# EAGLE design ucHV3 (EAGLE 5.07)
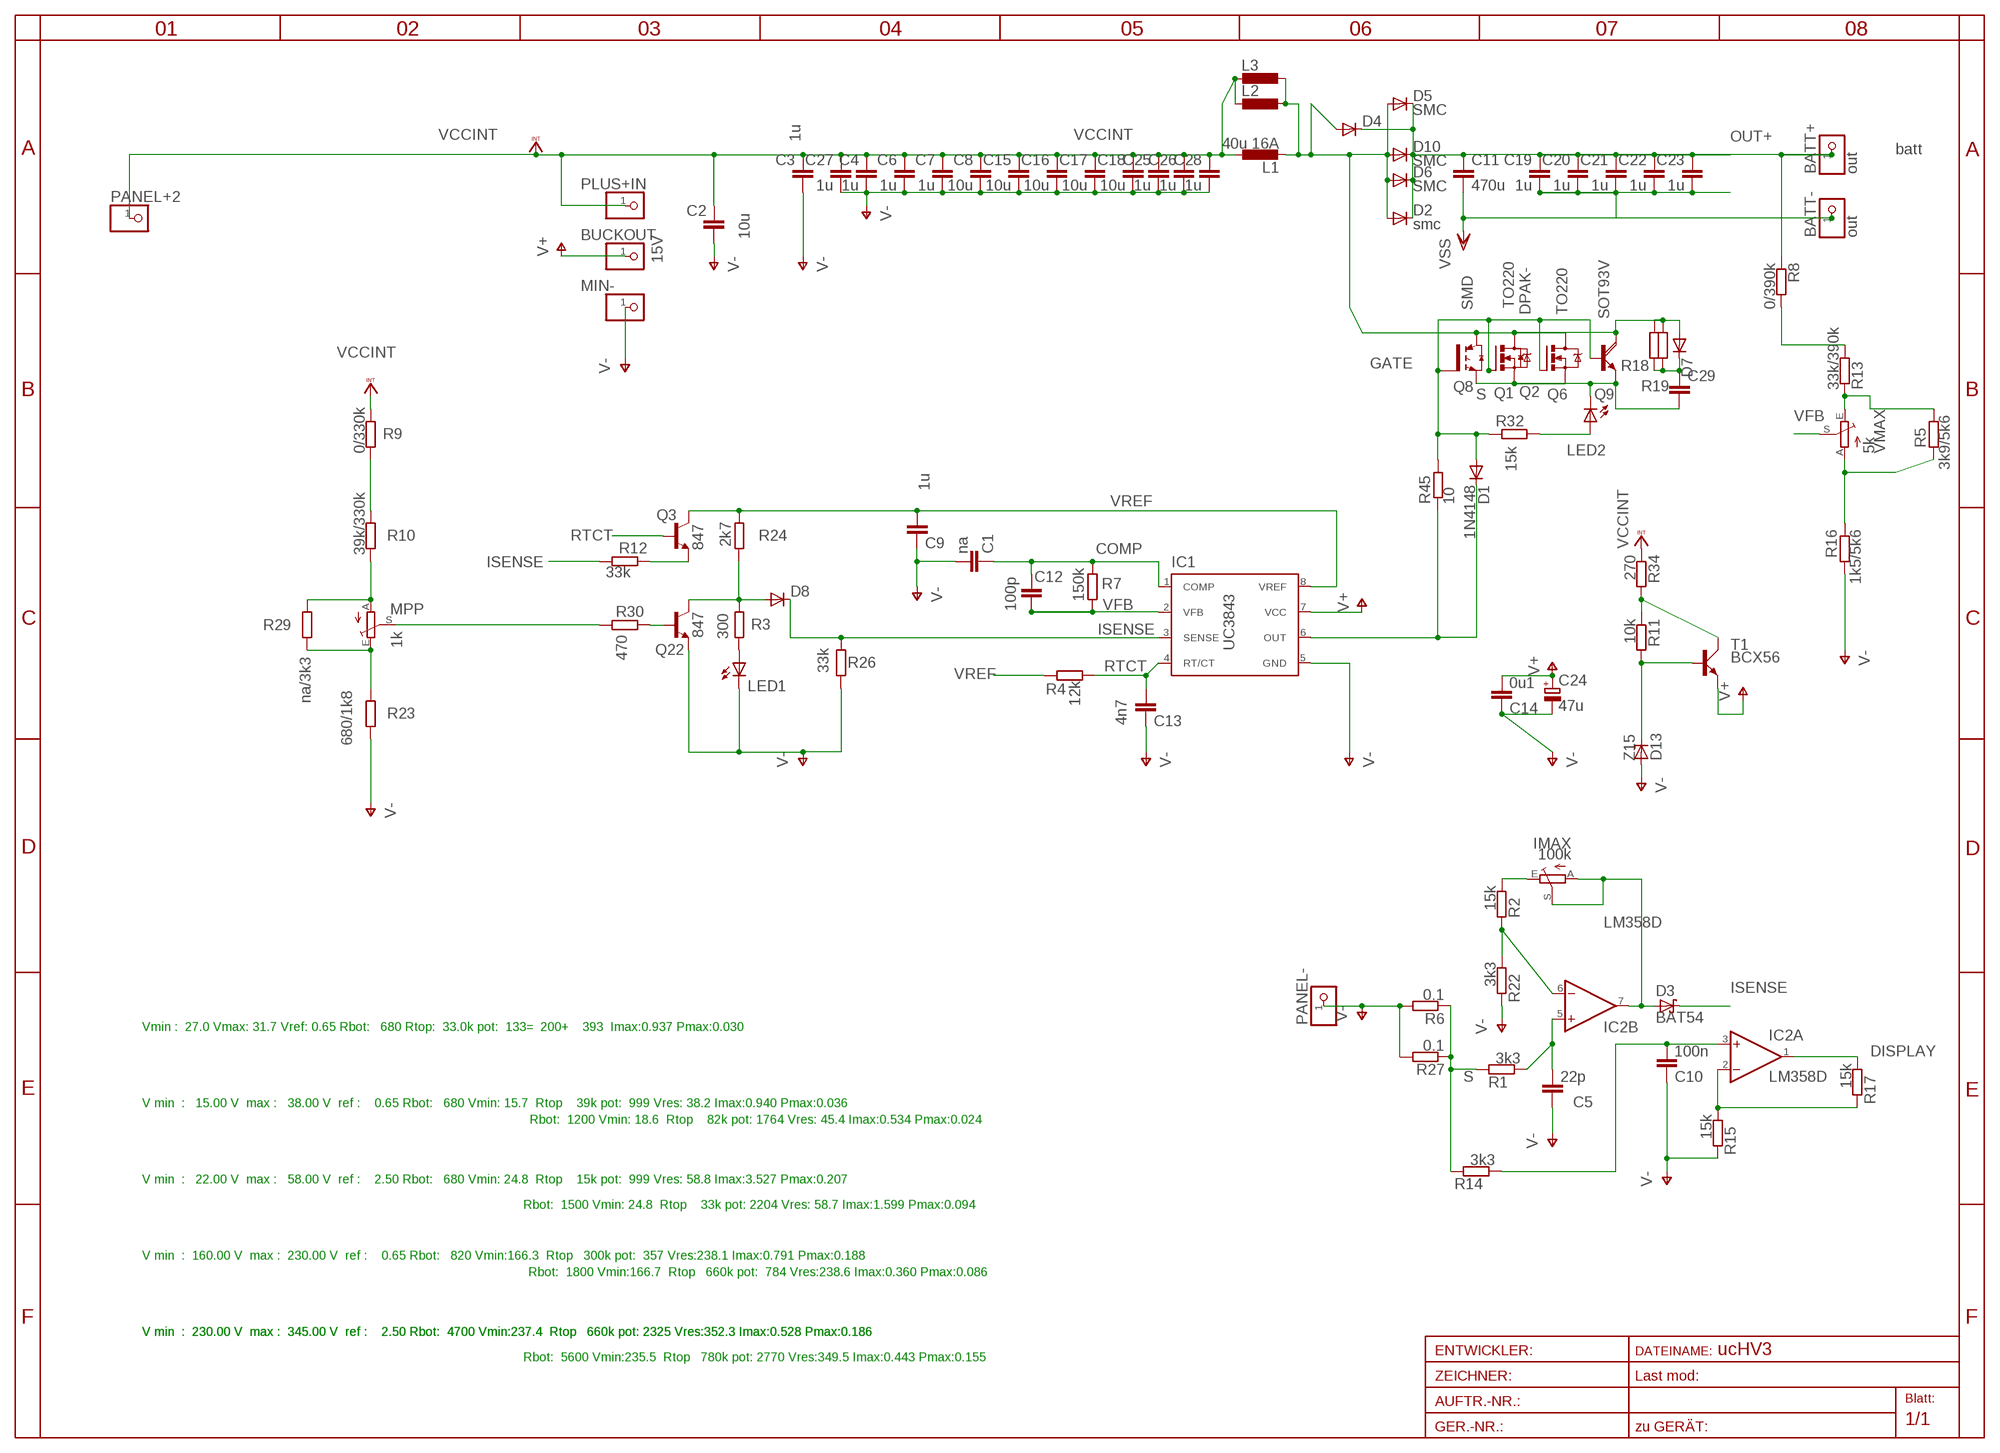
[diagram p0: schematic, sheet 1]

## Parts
BATT+  out  PINHD-1X12MM2  [1X2MM2]
BATT-  out  PINHD-1X12MM2  [1X2MM2]
BUCKOUT  15V  PINHD-1X11MM0  [1X1MM0]
C1  na  C-EUC0805  [C0805]
C2  10u  C-EUC058MLCC  [C058-020X040]
C3  1u  C-EUC058MLCC  [C058-020X040]
C4  1u  C-EUC058MLCC  [C058-020X040]
C5  22p  C-EUC0805  [C0805]
C6  1u  C-EUC058MLCC  [C058-020X040]
C7  1u  C-EUC058MLCC  [C058-020X040]
C8  10u  C-EUC058MLCC  [C058-020X040]
C9  1u  C-EUC1206  [C1206]
C10  100n  C-EUC1206  [C1206]
C11  470u  C-EU075-052X106  [C075-052X106]
C12  100p  C-EUC0805  [C0805]
C13  4n7  C-EUC0805  [C0805]
C14  0u1  C-EUC1206  [C1206]
C15  10u  C-EUC058MLCC  [C058-020X040]
C16  10u  C-EUC058MLCC  [C058-020X040]
C17  10u  C-EUC058MLCC  [C058-020X040]
C18  10u  C-EUC058MLCC  [C058-020X040]
C19  1u  C-EUC1206  [C1206]
C20  1u  C-EUC1206  [C1206]
C21  1u  C-EUC1206  [C1206]
C22  1u  C-EUC1206  [C1206]
C23  1u  C-EUC1206  [C1206]
C24  47u  CPOL-EUSANYO_SMD_C6  [SANYO-OSCON_SMD_C6]
C25  1u  C-EUC058MLCC  [C058-020X040]
C26  1u  C-EUC058MLCC  [C058-020X040]
C27  1u  C-EUC058MLCC  [C058-020X040]
C28  1u  C-EUC058MLCC  [C058-020X040]
C29  C-EU075-032X103  [C075-032X103]
D1  1N4148  DIODE-MINIMELF  [MINIMELF]
D2  smc  DIODE-SMC  [SMC]
D3  BAT54  [SOT23]
D4  DIODE-TO220H  [TO220AC]
D5  SMC  DIODE-SMC  [SMC]
D6  SMC  DIODE-SMC  [SMC]
D7  DIODE-DO34-7  [DO34-7]
D8  DIODE-SOT23  [SOT23]
D10  SMC  DIODE-SMC  [SMC]
D13  Z15  ZENER-DIODESOD80C  [SOD80C]
IC1  UC3843  UC1843D8  [SO-08]
IC2  LM358D  [SO08]
IMAX  100k  TRIM_EU-S64W  [S64W]
L1  40u 16A  L-EURNG  [RING]
L2  L-EUCEP150  [CEP150]
L3  L-EUCEP150  [CEP150]
LED1  LEDCHIPLED_1206  [CHIPLED_1206]
LED2  LEDCHIPLED_1206  [CHIPLED_1206]
MIN-  PINHD-1X11MM0  [1X1MM0]
MPP  1k  TRIM_EU-S64W  [S64W]
PANEL+2  PINHD-1X11MM6  [1X1MM8]
PANEL-  PINHD-1X12MM2  [1X2MM2]
PLUS+IN  PINHD-1X11MM0  [1X1MM0]
Q1  TO220  IRF740220  [TO220BV]
Q2  DPAK-  N-HEXFET_DPAK-  [TO252]
Q3  847  BC847ASMD  [SOT23]
Q6  TO220  IRF740220  [TO220BV]
Q8  SMD  IRG4BC15UD-S  [D2PACK]
Q9  SOT93V  TIP142SOT93V  [SOT93V]
Q22  847  BC847ASMD  [SOT23]
R1  3k3  R-EU_R0805  [R0805]
R2  15k  R-EU_R0805  [R0805]
R3  300  R-EU_R0805  [R0805]
R4  12k  R-EU_R0805  [R0805]
R5  3k9/5k6  R-EU_R0805  [R0805]
R6  0.1  R-EU_0207/10  [0207/10]
R7  150k  R-EU_R0805  [R0805]
R8  0/390k  R-EU_R1206  [R1206]
R9  0/330k  R-EU_R1206  [R1206]
R10  39k/330k  R-EU_R1206  [R1206]
R11  10k  R-EU_R1206  [R1206]
R12  33k  R-EU_0207/10  [0207/10]
R13  33k/390k  R-EU_R1206  [R1206]
R14  3k3  R-EU_R0805  [R0805]
R15  15k  R-EU_R1206  [R1206]
R16  1k5/5k6  R-EU_R0805  [R0805]
R17  15k  R-EU_R0805  [R0805]
R18  R-EU_0204/7  [0204/7]
R19  R-EU_0204/7  [0204/7]
R22  3k3  R-EU_R0805  [R0805]
R23  680/1k8  R-EU_R0805  [R0805]
R24  2k7  R-EU_R0805  [R0805]
R26  33k  R-EU_R0805  [R0805]
R27  0.1  R-EU_R3216  [R3216]
R29  na/3k3  R-EU_R1203  [R1203]
R30  470  R-EU_R0805  [R0805]
R32  15k  R-EU_R0805  [R0805]
R34  270  R-EU_0617/17  [0617/17]
R45  10  R-EU_R0805  [R0805]
T1  BCX56  [SOT223]
VMAX  5k  TRIM_EU-S64W  [S64W]

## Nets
COMP: C1.1 C12.2 IC1.1(COMP) R7.1
DISPLAY: IC2.1(A:OUT) R17.1
DQ18: D2.A D4.A D5.A D6.A D7.A D10.A L1.2 L2.1 L3.1 Q1.D Q2.3(D) Q6.D Q8.2(C) Q9.C R18.2 R19.2
GATE: D1.A Q1.G Q2.1(G) Q6.G Q8.1(G) Q9.B R32.1 R45.2
ISENSE: D3.3(C) D8.3(C) IC1.3(SENSE) R12.1 R26.1
N$1: C5.2 IC2.5(B:+IN) R1.1
N$2: IMAX.E R2.1
N$3: Q22.1(B) R30.1
N$4: LED1.A R3.2
N$5: LED2.A R32.2
N$6: R8.2 R13.2
N$7: D13.C R11.2 T1.1(B)
N$9: Q3.2(E) R12.2
N$10: C10.2 IC2.3(A:+IN) R14.1
N$11: IC2.2(A:-IN) R15.1 R17.2
N$21: R5.2 R16.1 VMAX.A
N$22: D3.1(A) IC2.7(B:OUT) IMAX.A IMAX.S
N$23: R11.1 R34.2 T1.2(C)
N$25: D1.C IC1.6(OUT) R45.1
N$27: IC2.6(B:-IN) R2.2 R22.1
N$30: R9.1 R10.2
N$32: MPP.A R10.1 R29.1
N$34: MPP.E R23.2 R29.2
N$37: R5.1 R13.1 VMAX.E
N$71: D8.1(A) Q22.3(C) R3.1 R24.2
OUT+: BATT+.1 C11.1 C19.1 C20.1 C21.1 C22.1 C23.1 D2.C D4.C D5.C D6.C D10.C R8.1
PRB1: MPP.S R30.2
RTCT: C13.2 IC1.4(RT/CT) Q3.1(B) R4.1
S: C29.2 LED2.C Q1.S Q2.2(S) Q6.S Q8.3(E) Q9.E R1.2 R6.1 R14.2 R27.1
SNUB: C29.1 D7.C R18.1 R19.1
V+: BUCKOUT.1 C14.2 C24.+ IC1.7(VCC) T1.3(E)
V-: BATT-.1 C1.2 C2.2 C3.2 C4.2 C5.1 C6.2 C7.2 C8.2 C9.1 C10.1 C11.2 C13.1 C14.1 C15.2 C16.2 C17.2 C18.2 C19.2 C20.2 C21.2 C22.2 C23.2 C24.- C25.2 C26.2 C27.2 C28.2 D13.A IC1.5(GND) LED1.C MIN-.1 PANEL-.1 Q22.2(E) R6.2 R15.2 R16.2 R22.2 R23.1 R26.2 R27.2 ; supply symbol labelled VSS
VCCINT: C2.1 C3.1 C4.1 C6.1 C7.1 C8.1 C15.1 C16.1 C17.1 C18.1 C25.1 C26.1 C27.1 C28.1 L1.1 L2.2 L3.2 PANEL+2.1 PLUS+IN.1 R9.2 R34.1
VFB: C12.1 IC1.2(VFB) R7.2 VMAX.S
VREF: C9.2 IC1.8(VREF) Q3.3(C) R4.2 R24.1

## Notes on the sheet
- batt
- Vmin :  27.0 Vmax: 31.7 Vref: 0.65 Rbot:   680 Rtop:  33.0k pot:  133=  200+    393  Imax:0.937 Pmax:0.030
- V min  :   15.00 V  max :   38.00 V  ref :    0.65 Rbot:   680 Vmin: 15.7  Rtop    39k pot:  999 Vres: 38.2 Imax:0.940 Pmax:0.036
- Rbot:  1200 Vmin: 18.6  Rtop    82k pot: 1764 Vres: 45.4 Imax:0.534 Pmax:0.024
- V min  :   22.00 V  max :   58.00 V  ref :    2.50 Rbot:   680 Vmin: 24.8  Rtop    15k pot:  999 Vres: 58.8 Imax:3.527 Pmax:0.207
- Rbot:  1500 Vmin: 24.8  Rtop    33k pot: 2204 Vres: 58.7 Imax:1.599 Pmax:0.094
- V min  :  160.00 V  max :  230.00 V  ref :    0.65 Rbot:   820 Vmin:166.3  Rtop   300k pot:  357 Vres:238.1 Imax:0.791 Pmax:0.188
- Rbot:  1800 Vmin:166.7  Rtop   660k pot:  784 Vres:238.6 Imax:0.360 Pmax:0.086
- V min  :  230.00 V  max :  345.00 V  ref :    2.50 Rbot:  4700 Vmin:237.4  Rtop   660k pot: 2325 Vres:352.3 Imax:0.528 Pmax:0.186 | V min  :  230.00 V  max :  345.00 V  ref :    2.50 Rbot:  4700 Vmin:237.4  Rtop   660k pot: 2325 Vres:352.3 Imax:0.528 Pmax:0.186
- Rbot:  5600 Vmin:235.5  Rtop   780k pot: 2770 Vres:349.5 Imax:0.443 Pmax:0.155

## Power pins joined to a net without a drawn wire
V+: IC2.8(P:V+)
V-: IC2.4(P:V-)

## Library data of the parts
BATT+ BATT- BUCKOUT MIN- PANEL+2 PANEL- PLUS+IN = pinhead:PINHD-1X1: PIN HEADER
C1-C23 C25-C29 = rcl:C-EU: CAPACITOR, European symbol
C24 = rcl:CPOL-EU: POLARIZED CAPACITOR, European symbol
D1 D2 D4-D8 D10 = diode:DIODE-: DIODE
D3 = diode:BAT54: Schottky Diodes
D13 = diode:ZENER-DIODE: Z-Diode
IC1 = texas:UC1843D8: PULSE WIDTH MODULATOR
IC2 = linear:LM358: OP AMP also LM158; LM258; LM2904 Source: http://cache.national.com/ds/LM/LM158.pdf
IMAX MPP VMAX = pot:TRIM_EU-: POTENTIOMETER
L1-L3 = rcl:L-EU: INDUCTOR, European symbol
LED1 LED2 = led:LED: LED
Q1 Q6 = transistor-power:IRF740: N-CHANNEL MOS FET
Q2 = transistor-power:N-HEXFET_?-*: HEXFET® Power MOSFET
Q3 Q22 = transistor-npn:BC847*: NPN Transistor
Q8 = transistor-power:IRG4BC15UD-: INSULATED GATE BIPOLAR TRANSISTOR WITH ULTRAFAST SOFT RECOVERY DIODE
Q9 = transistor-power:TIP142: NPN DARLINGTON TRANSISTOR
R1-R10 R12-R19 R22-R24 R26 R27 R29 R30 R34 = rcl:R-EU_: RESISTOR, European symbol
R11 R32 R45 = rcl-2:R-EU_: RESISTOR, European symbol
T1 = transistor-power:BCX56

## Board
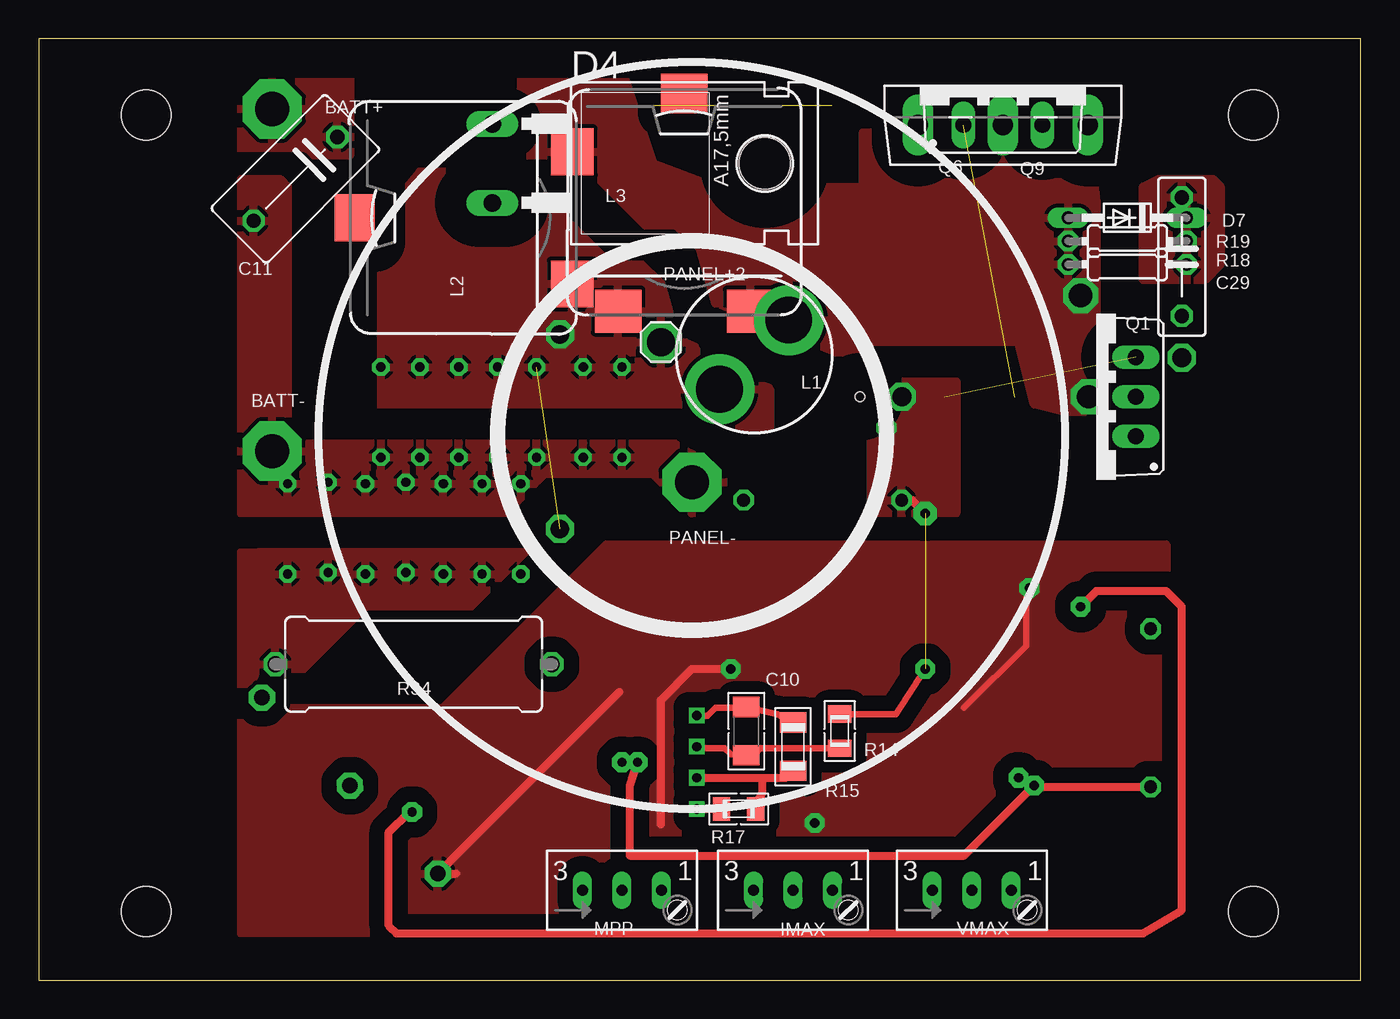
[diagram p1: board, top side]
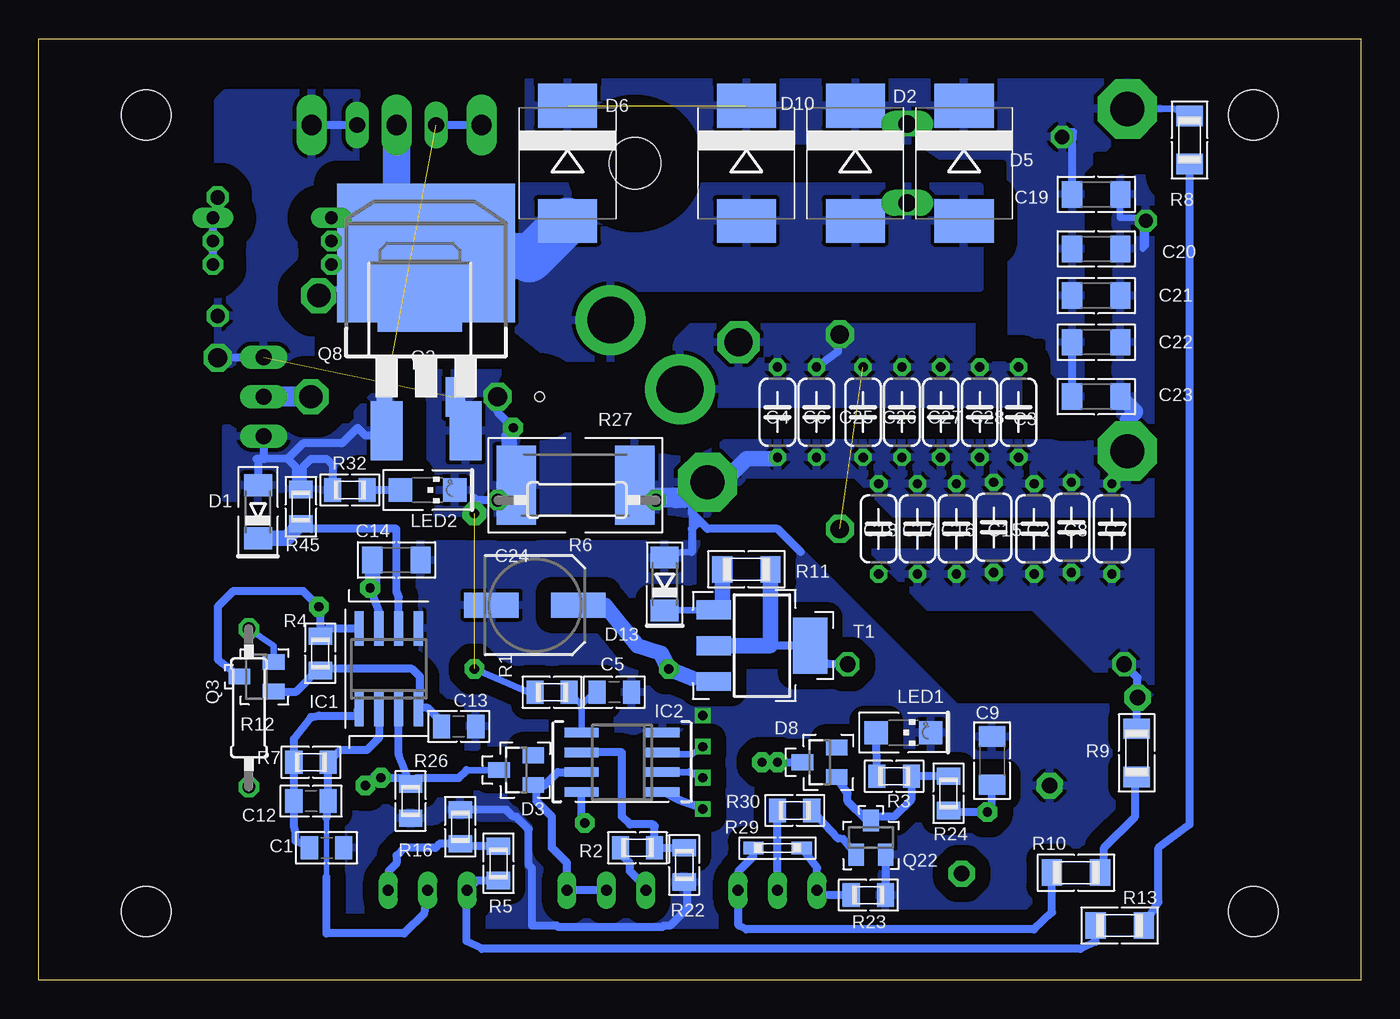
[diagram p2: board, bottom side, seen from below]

Size 85 x 60.5 mm. Coordinates in mm from the lower left corner, seen from the top.
Outline: 0,0 85,0 85,60.5 0,60.5 0,0
Copper layers (1*16): Top 0.035mm / dielectric 1.5mm / Bottom 0.035mm
Design rules "default *": minimum track width 10mil, minimum drill 0.5mm, track to track 8mil, track to pad 8mil, pad to pad 8mil, via to via 8mil, smd to smd 8mil, copper to edge 2.5mm, drill to drill 8mil, minimum pad ring 10mil, minimum via ring 8mil, stop-mask expansion 4mil, vias tented up to drill 0mil, thermal gap 10mil
Holes 3.2 mm at 6.9,55.6 6.9,4.4 78.1,4.4 78.1,55.6
Holes 0.6 mm at 52.8,37.5

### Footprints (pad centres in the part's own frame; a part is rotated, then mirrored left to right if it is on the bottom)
1X2MM2 = drill 2.2 pad 3.81 octagon: 1 0,0
1X1MM0 = drill 1 pad 1.676 octagon: 1 0,0
C0805 = smd 1.1 x 1.5: 1 -1.1,0; 2 1.1,0
C058-020X040 = drill 0.6 octagon: 1 -2.9,0; 2 2.9,0
C1206 = smd 1.3 x 1.7: 1 -1.55,0; 2 1.55,0
C075-052X106 = drill 0.914 octagon: 1 -3.81,0; 2 3.81,0
SANYO-OSCON_SMD_C6 = smd 3.5 x 1.6: + 2.8,0; - -2.8,0
C075-032X103 = drill 0.914 octagon: 1 -3.81,0; 2 3.81,0
MINIMELF = smd 1.4 x 1.8: A 1.7,0; C -1.7,0
SMC = smd 2.8 x 3.8: A 3.7,0; C -3.7,0
SOT23 = smd 1 x 1.4: 1 -0.95,-1.1; 2 0.95,-1.1; 3 0,1.1
TO220AC = drill 1.118 long: A 2.54,-6.35; C -2.54,-6.35 | hole 3.302: 0,11.176
DO34-7 = drill 0.813 long: A 3.81,0; C -3.81,0
SOD80C = smd 1.4 x 1.8: A 1.7,0; C -1.7,0
SO-08 = smd 0.6 x 2.2: 1 -1.905,-2.6; 2 -0.635,-2.6; 3 0.635,-2.6; 4 1.905,-2.6; 5 1.905,2.6; 6 0.635,2.6; 7 -0.635,2.6; 8 -1.905,2.6
SO08 = smd 0.6 x 2.2: 1 -1.905,-2.6; 2 -0.635,-2.6; 3 0.635,-2.6; 4 1.905,-2.6; 5 1.905,2.6; 6 0.635,2.6; 7 -0.635,2.6; 8 -1.905,2.6
S64W = drill 0.7 long: A 2.54,1.27; E -2.54,1.27; S 0,1.27
RING = drill 3 pad 4 round: 1 -3.15,0; 2 3.15,0
CEP150 = smd 3 x 2.75: 1 -4.25,7; 2 4.25,7 | smd 3 x 2.55: 3 0,-7
CHIPLED_1206 = smd 1.5 x 1.5: A 0,-1.75; C 0,1.75
1X1MM8 = drill 1.8 pad 2.54 octagon: 1 0,0
TO220BV = drill 1.016 long: D 0,-2.54; G -2.54,-2.54; S 2.54,-2.54
TO252 = smd 1 x 1.6: 1 -2.28,-3.53 | smd 1.27 x 2.54: 2 2.28,-3.53 | smd 5.4 x 6.2: 3 0,3.77
D2PACK = smd 2.083 x 3.81: 1 -2.54,-8.89; 3 2.54,-8.89 | smd 11.43 x 8.89: 2 0,2.54
SOT93V = drill 1.3 pad 1.676 long: B -5.461,-2.54; C 0,-2.54; E 5.461,-2.54
R0805 = smd 1.1 x 1.5: 1 -1.1,0; 2 1.1,0
0207/10 = drill 0.813 octagon: 1 -5.08,0; 2 5.08,0
R1206 = smd 1.3 x 1.7: 1 -1.55,0; 2 1.55,0
0204/7 = drill 0.813 octagon: 1 -3.81,0; 2 3.81,0
R3216 = smd 2.54 x 5.08: 1 -3.81,0; 2 3.81,0
R1203 = smd 1.3 x 0.8: 1 -1.55,0; 2 1.55,0
0617/17 = drill 1.016 octagon: 1 -8.89,0; 2 8.89,0
SOT223 = smd 1.219 x 2.235: 1 -2.311,-3.099; 2 0,-3.099; 3 2.311,-3.099 | smd 3.6 x 2.2: 4 0,3.099

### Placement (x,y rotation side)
BATT+  15,56 0 top
BATT-  15,34 0 top
BUCKOUT  25.66,6.84 90 top
C1  66.5,8.5 0 bottom
C2  21,29 90 bottom
C3  22,36.5 270 bottom
C4  37.5,36.5 270 bottom
C5  48,18.5 180 bottom
C6  35,36.5 270 bottom
C7  16,29 90 bottom
C8  18.6,29.1 90 bottom
C9  23.7,14.1 270 bottom
C10  45.5,16 270 top
C11  16.5,51.5 225 top
C12  67.5,11.5 180 bottom
C13  58,16.3 180 bottom
C14  62,27 180 bottom
C15  23.6,29.1 90 bottom
C16  26,29 90 bottom
C17  28.5,29 90 bottom
C18  31,29 90 bottom
C19  17,50.5 0 bottom
C20  17,47 0 bottom
C21  17,44 0 bottom
C22  17,41 0 bottom
C23  17,37.5 0 bottom
C24  53.1,24.1 0 bottom
C25  32,36.5 270 bottom
C26  29.5,36.5 270 bottom
C27  27,36.5 270 bottom
C28  24.5,36.5 270 bottom
C29  73.5,46.5 270 top
D1  70.9,30.1 90 bottom
D2  32.5,52.5 270 bottom
D3  54.3,13.5 90 bottom
D4  35.5,52.5 270 top
D5  25.5,52.5 270 bottom
D6  51,52.5 270 bottom
D7  70,49 180 top
D8  34.8,14 90 bottom
D10  39.5,52.5 270 bottom
D13  44.76,25.46 90 bottom
IC1  62.5,20 0 bottom
IC2  47.5,14 90 bottom
IMAX  48.5,4.5 0 top
L1  46,40.2 45 top
L2  27.3,49 270 top
L3  41.5,50 180 top
LED1  29.4,15.9 270 bottom
LED2  60,31.5 270 bottom
MIN-  20,12.5 315.7 top
MPP  37.5,4.5 0 top
PANEL+2  40,41 0 top
PANEL-  42,32 90 top
PLUS+IN  14.34,18.16 90 top
Q1  68,37.5 90 top
Q2  60.5,41 0 bottom
Q3  71,19.5 90 bottom
Q6  62,57.5 0 top
Q8  60.1,44.2 0 bottom
Q9  62,57.5 0 top
Q22  31.49,9.16 0 bottom
R1  52,18.5 180 bottom
R2  46.5,8.5 0 bottom
R3  30,13.1 180 bottom
R4  66.9,21 90 bottom
R5  55.45,7.5 90 bottom
R6  50.4,30.84 0 bottom
R7  67.5,14 0 bottom
R8  11,54 270 bottom
R9  14.4,14.6 90 bottom
R10  18.3,6.9 0 bottom
R11  39.5,26.4 180 bottom
R12  71.5,17.5 90 bottom
R13  15.5,3.5 0 bottom
R14  51.5,16 90 top
R15  48.5,15 90 top
R16  57.9,9.85 90 bottom
R17  45,11 0 top
R18  70,46 180 top
R19  70,47.5 180 top
R22  43.5,7.4 270 bottom
R23  31.66,5.46 180 bottom
R24  26.5,12 90 bottom
R26  61.1,11.5 270 bottom
R27  50.5,31.8 0 bottom
R29  37.5,8.5 0 bottom
R30  36.4,10.9 180 bottom
R32  65,31.5 0 bottom
R34  24.1,20.3 0 top
R45  68.15,30.43 90 bottom
T1  38.5,21.5 270 bottom
VMAX  60,4.5 0 top

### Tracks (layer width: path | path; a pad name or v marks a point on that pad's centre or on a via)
COMP
  Bottom 0.5: C1.1 68.5,8.95 68.5,9.5 68.6,9.9 C12.2 R7.1 68.6,15.5 67.5,16.9 67,17 64.5,17 64.5,17.4 IC1.1
DISPLAY  (via drill 0.6)
  Top 0.5: v42.3,11 R17.1
  Bottom 0.5: IC2.1 43.91,11.6 v42.3,11
DQ18  (via drill 1.5 pad 1.2)
  Bottom 0.406: v67,44 61.4,46 61.4,46.89
  Bottom 0.5: Q2.3 60.5,45.1 61.4,46
  Bottom 1.27: v67.5,37.5 Q1.D
  Bottom 1.778: 62,47.04 Q9.C
  Bottom 2.54: Q8.2 61.4,46.89 62,47.04
  Bottom 3: Q8.2 53.54,46.54 53.47,46.34 D6.A
  pour Bottom (isolate 1.5, rank 2): 24.5,51 55.5,51 54.5,42 52,40 47,40 47,44.5 24.5,44.5
  pour Top (isolate 2): 53,54.5 67.5,54.5 68,50 68,37 67.5,36.5 66,36.5 64,37 63,41 53,41
  pour Top (isolate 1.5, rank 2): 54.5,51 54.5,42 52,40 43.5,43.5 42.5,47 41,48.5 39,48.5 34.5,53 31,53 31,58.5 37.5,58.5 39.5,52.5 43.5,51
GATE  (1 unrouted)
  Bottom 0.5: Q8.1 62.64,37.33 Q2.1 62.78,35.22 63,35 64,35 64.5,35.5 65.5,34.5 68,34.5 69,33.5 | R32.1 66.1,33.1 66.5,33.5 67.5,33.5 68,33 68,31.68 R45.2 68.03,31.53 | D1.A 70.9,33.4 71,33.5 70.5,33.5 | 69,33.5 68.5,33 68.5,32 68.03,31.53 | 68.03,31.53 68,31.5 | 69,33.5 70.5,33.5 | 70.5,33.5 70.5,35 | Q9.B Q6.G
  pour Bottom (isolate 1.5): 62.5,37.5 63.5,37.5 64.5,36.5 64.5,36 65,35.5 73,35.5 73,31 66,31 65.5,31.5 65.5,32 63.5,34 62,34 62,36.5
ISENSE  (via drill 0.6 pad 1.27)
  Top 0.5: v38.5,14 38,12.5 38,8 59.5,8 v64,12.5 64.08,12.42 R12.1
  Bottom 0.406: 57.5,13.5 D3.3
  Bottom 0.5: IC1.3 61.87,14.46 R26.1 | D8.3 v37.5,14 v38.5,14 | R26.1 61.5,13 v63,13 63.5,13 v64,12.5 | 57.5,13.5 58,13 60.7,13 R26.1
N$1
  Bottom 0.406: IC2.5 50.1,17.7 | 50.1,17.7 R1.1 | C5.2 49.3,18.5 50.1,17.7
N$2
  Bottom 0.5: IMAX.E 45.96,5.96 47,7 47,7.5 47.5,8 47.5,8.4 R2.1
N$3
  Bottom 0.5: Q22.1 33.26,9.06 33.6,9.1 R30.1
N$4
  Bottom 0.5: R3.2 LED1.A
N$5
  Bottom 0.5: LED2.A R32.2
N$6
  Bottom 0.5: R8.2 11,10 13,8.5 13,5 R13.2
N$7
  Bottom 0.406: D13.C 40.84,23.76 41.02,23.77 T1.1
  Bottom 1: R11.2 41.05,23.8 41.02,23.77
N$9
  Bottom 0.406: Q3.2 69.9,21.48 R12.2
N$10  (via drill 0.6)
  Top 0.406: v42.3,15 42.6,14.9 44.1,14.9 44.5,14.5 C10.2 46,14.5 46.4,14.9 R14.1
  Bottom 0.406: IC2.3 44.63,14.63 44.5,14.5 43,14.5 v42.3,15
N$11  (via drill 0.6)
  Top 0.406: 48.5,13.5 R15.1
  Top 0.5: R17.2 46.1,11.4 46.5,12 46.5,13 | 48.5,13.5 48,13 46.5,13 | v42.3,13 46.5,13
  Bottom 0.406: 43.13,13.37 IC2.2
  Bottom 0.5: v42.3,13 43.13,13.37
N$21
  Bottom 0.5: R5.2 57.75,8.6 R16.1 59.25,8.75 59.5,8.5 61.5,8.5 62,8 62,7.5 62.5,7 62.5,5.81 VMAX.A
N$22
  Bottom 0.5: IMAX.S IMAX.A 51.04,7.54 52,8.5 52,10.5 53,11.5 53,12.45 D3.1 52.85,12.5 52.5,12.5 51.63,13.37 IC2.7
N$23
  Bottom 0.5: R34.2 34.3,20.3 35.5,21.5 37.9,21.5 37.95,21.55
  Bottom 1: T1.2 38,21.5 37.95,21.55 R11.1
N$25
  Bottom 0.5: IC1.6 61.87,24.64 62,25 62,29 67.48,29 R45.1
  Bottom 1: D1.C 69.08,28.4 R45.1
N$27
  Bottom 0.5: IC2.6 47.5,14.63 47.5,10.5 47,10 45.5,10 45.4,9.9 R2.2 R22.1
N$30
  Bottom 0.5: R10.2 16.5,7 16.5,8.5 14.5,10.5 14.5,13.05 R9.1
N$32
  Bottom 0.5: MPP.A 40.04,6.04 | R29.1 39.05,7.95 40,7 40,5.81 MPP.A | R10.1 19.85,4.35 21,3.25 39.5,3.25 40,3.5 40,5.73 MPP.A
N$34
  Bottom 0.5: R23.2 34.77,5.46 MPP.E 34.96,7.21 R29.2
N$37
  Top 0.5: VMAX.E 57.5,5.73
  Bottom 0.5: VMAX.E 57.4,5.83 | R5.1 56.83,6.4 VMAX.E | R13.1 17.05,2.45 18,2 56.5,2 57.5,2.5 57.5,5.73 VMAX.E
N$71
  Bottom 0.5: R24.2 R3.1 28.9,11.6 30,10.5 31.25,10.5 Q22.3 31.76,10.26 33,11.5 33,12 D8.1
OUT+  (1 unrouted)
  Bottom 0.406: R8.1 11.05,55.55 12,56 12.5,56 BATT+.1
  Bottom 0.5: C23.1 C22.1 | C19.1 18.55,53.45 18.5,54.5 18.89,54.5 C11.1
  pour Bottom (isolate 1.5, rank 4): 13,55 13,59.5 53.5,59.5 53.5,54 28.5,54 22.5,50 22.5,41 arc46 18,36.5 18,52 15.5,54.5
  pour Top (isolate 1.5, rank 4): 13,53 13,58.5 20,58.5 20,53
PRB1
  Bottom 0.5: MPP.S R30.2
RTCT
  Bottom 0.406: 69.35,18.5 Q3.1
  Bottom 0.5: 67,20 R4.1 | 67,20 61,20 60.5,19.5 60.5,17.5 IC1.4 60.49,17.5 60,17.5 59.1,16.6 C13.2 | 67,20 68.5,18.5 69.35,18.5
S  (via drill 0.6 pad 1.27, 0.6 pad 1.5, 1.2 pad 1.8)  (2 unrouted)
  Top 0.406: R14.2 55.1,17.1 v57,20
  Top 0.5: v73.5,40 73.54,40.04 | R6.1 56.16,30.84 v57,30
  Bottom 0.406: R1.2 53.5,18.5 v57,20
  Bottom 0.5: Q6.S Q9.E | 57.11,35.11 Q8.3 57.56,36.81 Q2.2 | v55.5,37.5 55.5,36.5 v54.5,35.5 54.5,34.5 55,35 55,30.97 R6.1 56.84,30.84 57,31 | v73.5,40 70.58,40 Q1.S
  Bottom 1.27: R6.1 54.31,30.95 R27.1
  pour Bottom (isolate 1.5): 64.5,57 73,57 73.5,56.5 73.5,40 72,39 67.5,39 67.5,49 64.5,52
  pour Top: 54,38.5 59,38.5 59,36.5 59,30 53.5,30 53.5,35.5
  pour Bottom (isolate 1.5, rank 3): 51,39 60,39 60,30 51,30
SNUB
  Bottom 0.5: C29.1 73.5,49.31 D7.C R19.1 R18.1
  pour Top: 72,51.5 75.5,51.5 76,51 76,46 75,45 71,45 71,51
V+  (via drill 0.6 pad 1.27)
  Top 0.406: v63.7,25.2 63.5,25 63.5,21.5 59.5,17.5
  Top 0.5: 26.84,6.84 BUCKOUT.1 37.31,18.5 | v49.9,10.1 49.8,10 | v44.5,20 42,20 40,18 40,10
  Bottom 0.406: 43,19.39 T1.3 | 48.6,24.1 C24.+
  Bottom 0.5: IC1.7 63.13,23.66 v63.7,25.2 | IC2.8 50.1,10.4 v49.9,10.1
  Bottom 1: 43,19.39 v44.5,20 45,21 46.5,21.5 48.6,24.1 | C14.2 63.55,25.35 v63.7,25.2
  pour Top (isolate 1): 36.5,28 72.5,28 72.5,3 13,3 13,17.5 26,17.5
V-  (via drill 0.6)
  Top 0.406: v42.3,17 43,17 43.5,17.5 45,17.5 C10.1 47.5,17.1 R15.2
  Bottom 0.406: 43,29.7 43,27.5 43.71,27.5 D13.A | C11.2 13.81,47.19 14,47 14,49 15.5,49 15.5,50.45 C19.2
  Bottom 0.5: R23.1 30.5,5.5 30.5,5 30.54,5.97 Q22.2 | R16.2 54.95,10.95 54.5,10.5 54.3,10.5 53.5,9.7 53.5,7.4 53.3,7.2 53.3,3.5 51.7,3.5 51.6,3.4 44.9,3.4 44.8,3.5 44.4,3.5 43.3,4.6 43.3,6.1 R22.2 | 43,31 43,30 42.5,29.5 | 42.5,29.5 42,29 37.5,29 36,27.5 | 43,27.5 43,29 42.5,29.5 | R6.2 43.66,30.84 43.5,31
  Bottom 1: PANEL-.1 41,32 39.5,33.5 37.6,33.5 C4.2 | BATT-.1 15,36 14.5,36.5 14.5,36.55 C23.2
  Bottom 1.27: 43,31 43.5,31 | 43.5,31 46.69,31 R27.2 | 43.5,31 44,30.95
  pour Bottom (isolate 1): 36.5,28 72.5,28 72.5,3 14.5,3 14.5,17.5 26,17.5
  pour Bottom (isolate 2): 13,51.5 15.5,51.5 16,51 16,34.5 47,34.5 47,30.5 43.5,30 42,30 39.5,32.5 32.5,32.5 30,30 13,30
  pour Top (isolate 2): 13,51.5 15.5,51.5 16,51 16,34.5 44,34.5 44,30.5 43.5,30 42,30 39.5,32.5 32.5,32.5 30,30 13,30
VCCINT  (via drill 1.2)  (1 unrouted)
  Bottom 0.5: C6.1 33.6,40.4 v33.5,41.5 | R9.2 14.4,18.1 PLUS+IN.1 14.34,19.43 R34.1
  other vias: 33.5,29
  pour Bottom (isolate 2, rank 2): 13.5,28 30,28 33,31.5 40,31.5 40,29 36.5,29 31.5,24 21,24 15,18 14,18 13.5,18.5
  pour Bottom (isolate 2, rank 3): 25,42.5 42.5,42.5 47,38 47,35.5 39.5,35.5 39,36 22,36.5 22,39.5 25,39.5
  pour Top (isolate 2, rank 2): 13,27.5 30,28 33,31.5 40,31.5 40,29 36.5,29 31.5,24 21,24 15,18 13,18
  pour Top (isolate 2, rank 3): 24.5,52 34,52 47,38 47,35.5 39.5,35.5 39,36 22,36.5 22,49
VFB
  Bottom 0.35: 66.5,6.63 66.5,10.4
  Bottom 0.5: VMAX.S 60.2,4.29 61.5,3 66.5,3 66.5,6.63 | 66.5,10.4 66.4,11.16 C12.1 R7.2 65.6,14.8 63.9,14.8 63.1,15.6 63.1,16.36 IC1.2
VREF  (via drill 0.6 pad 1.27)
  Top 0.5: v24,10.8 23.8,10.8 22.5,9.5 22.5,3.5 23,3 71,3 73.5,4.5 73.5,24 72.5,25 68,25 v67,24
  Bottom 0.5: IC1.8 66.4,22.6 R4.2 66.9,23.4 67,23.5 v67,24 68,25 72.5,25 73.5,24 73.5,20.6 Q3.3 | C9.2 23.7,10.8 v24,10.8 26.5,10.8 R24.1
